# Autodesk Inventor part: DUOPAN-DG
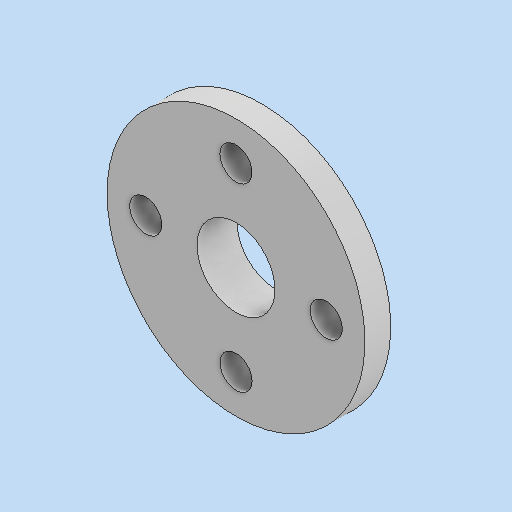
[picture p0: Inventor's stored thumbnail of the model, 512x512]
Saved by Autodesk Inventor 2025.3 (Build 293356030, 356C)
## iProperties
Created: 2016-09
Part Number: DUOPAN-DG
Material: Generico
Document SubType Name: Modeling
Designer: Ryzen5700u
Density: 1 g/cm^3
Appearance: Default
Author: Ryzen5700u
Revision Number: 1LAST_VERSION
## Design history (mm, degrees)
feature "Solido1"
node "Solido2"
